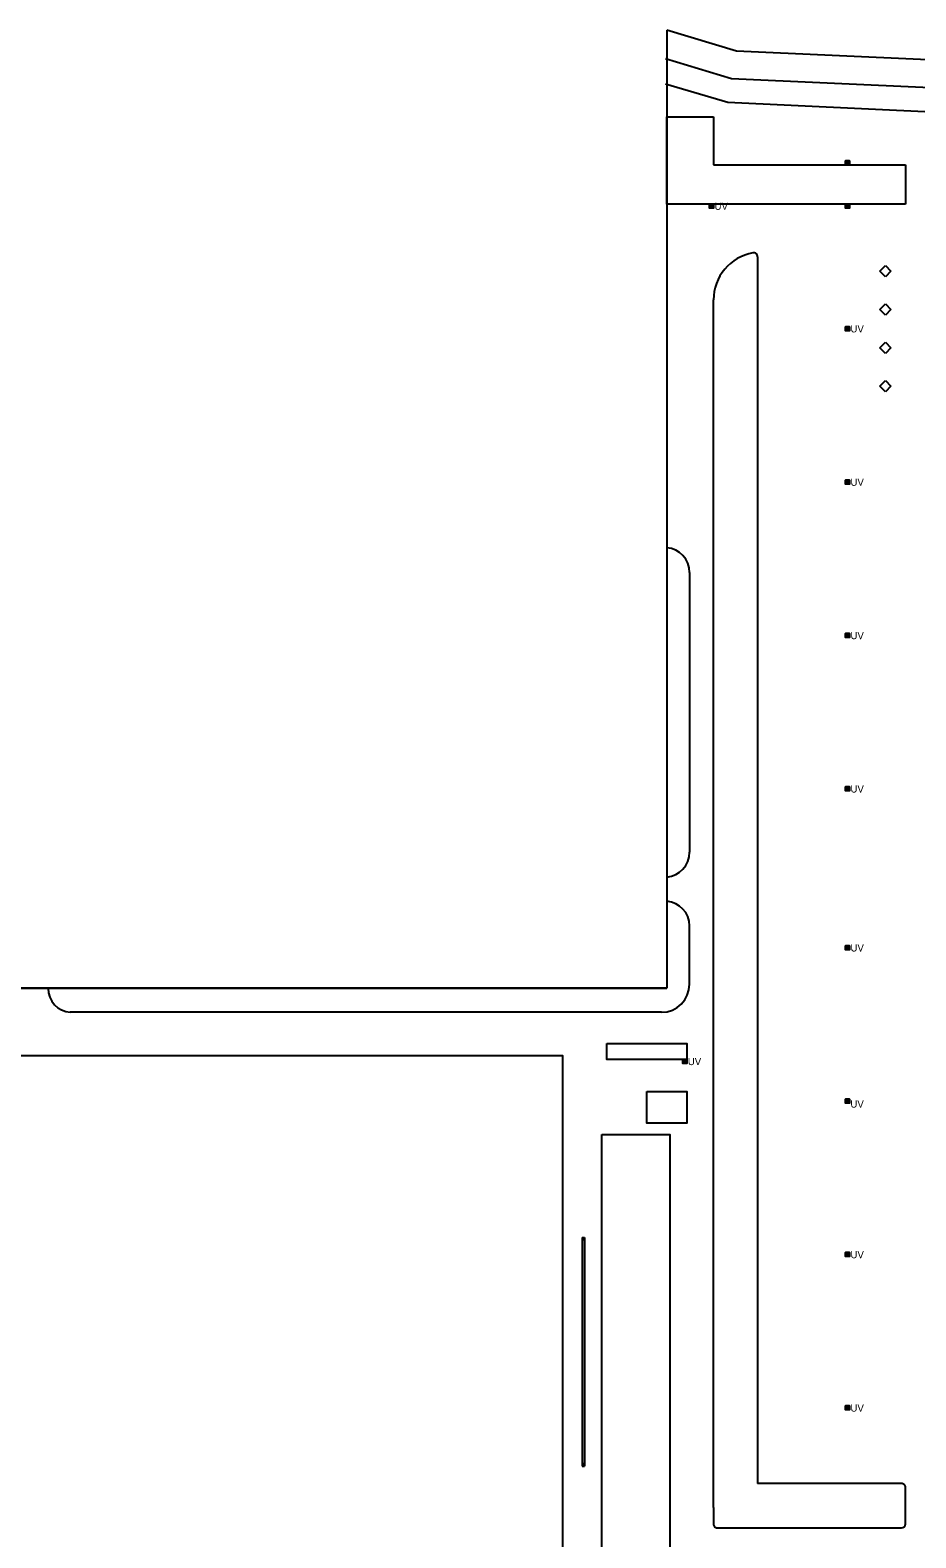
# Model space of a CAD drawing. Extents: x -264222 to -263676, y -1242344 to -1242060.
# Drawn here: x -264039.2 to -263928.3, y -1242248.3 to -1242059.5 of the extents above; entities that cross this region are included whole.
import ezdxf

# ---------------------------------------------------------------- set-up
doc = ezdxf.new("R2010")
doc.units = 0
doc.layers.add('PROJEKT_DRS_OBRUBNIKY_KOMUNIKACIE', color=7, linetype='Continuous')
doc.layers.add('PROJEKT_DRS_UV_STAVBY', color=7, linetype='Continuous')

msp = doc.modelspace()

# ---------------------------------------------------------------- linework, layer by layer
at = {"layer": 'PROJEKT_DRS_OBRUBNIKY_KOMUNIKACIE'}
for p, q in [((-263950.75, -1242062.15), (-263959.47, -1242059.53)), ((-263959.47, -1242059.53), (-263959.47, -1242179.48)), ((-263926.77, -1242063.25), (-263950.75, -1242062.15)), ((-263959.47, -1242071.38), (-263959.47, -1242070.38)), ((-263959.47, -1242070.38), (-263953.62, -1242070.38)), ((-263953.62, -1242070.38), (-263953.62, -1242076.38)), ((-263959.47, -1242076.38), (-263959.47, -1242071.38)), ((-263959.47, -1242081.31), (-263959.47, -1242076.38)), ((-263953.62, -1242076.38), (-263929.58, -1242076.38)), ((-263929.58, -1242076.38), (-263929.58, -1242081.31)), ((-263953.62, -1242081.31), (-263959.47, -1242081.31)), ((-263929.58, -1242081.31), (-263953.62, -1242081.31)), ((-263948.09, -1242087.9), (-263948.09, -1242241.46)), ((-263932.8, -1242089.71), (-263932.09, -1242089)), ((-263932.09, -1242089), (-263931.39, -1242089.71)), ((-263932.09, -1242090.41), (-263932.8, -1242089.71)), ((-263931.39, -1242089.71), (-263932.09, -1242090.41)), ((-263953.62, -1242244.46), (-263953.62, -1242093.31)), ((-263932.8, -1242094.51), (-263932.09, -1242093.8)), ((-263932.09, -1242095.21), (-263932.8, -1242094.51)), ((-263932.09, -1242093.8), (-263931.39, -1242094.51)), ((-263931.39, -1242094.51), (-263932.09, -1242095.21)), ((-263932.8, -1242099.31), (-263932.09, -1242098.6)), ((-263932.09, -1242098.6), (-263931.39, -1242099.31)), ((-263932.09, -1242100.01), (-263932.8, -1242099.31)), ((-263931.39, -1242099.31), (-263932.09, -1242100.01)), ((-263932.8, -1242104.11), (-263932.09, -1242103.4)), ((-263932.09, -1242104.81), (-263932.8, -1242104.11)), ((-263932.09, -1242103.4), (-263931.39, -1242104.11)), ((-263931.39, -1242104.11), (-263932.09, -1242104.81)), ((-263959.47, -1242106.15), (-263959.47, -1242179.48)), ((-263956.62, -1242127.42), (-263956.62, -1242162.45)), ((-263956.62, -1242178.98), (-263956.62, -1242171.65)), ((-263959.47, -1242179.48), (-264131.57, -1242179.48)), ((-264131.57, -1242179.48), (-263959.47, -1242179.48)), ((-263959.47, -1242179.48), (-264077.23, -1242179.48)), ((-263960.12, -1242182.48), (-264034.16, -1242182.48)), ((-263930.08, -1242241.46), (-263948.09, -1242241.46)), ((-263929.58, -1242246.53), (-263929.58, -1242241.96)), ((-263953.62, -1242244.46), (-263953.62, -1242246.53)), ((-263953.12, -1242247.03), (-263930.08, -1242247.03))]:
    msp.add_line(p, q, dxfattribs=at)
for points in [[(-263863.95, -1242065.11), (-263895.45, -1242062.32), (-263915.2, -1242060.92), (-263926.77, -1242063.25), (-263950.75, -1242062.15), (-263959.47, -1242059.53)], [(-263864.26, -1242068.59), (-263895.73, -1242065.81), (-263914.97, -1242064.45), (-263926.5, -1242066.77), (-263951.34, -1242065.63), (-263959.61, -1242063.14)], [(-263864.52, -1242071.58), (-263895.97, -1242068.8), (-263914.78, -1242067.47), (-263926.27, -1242069.78), (-263951.84, -1242068.6), (-263959.61, -1242066.28)], [(-263966.97, -1242186.38), (-263956.97, -1242186.38), (-263956.97, -1242188.38), (-263966.97, -1242188.38), (-263966.97, -1242186.38)], [(-264042.57, -1242294.03), (-263972.47, -1242294.03), (-263972.47, -1242187.93), (-264042.57, -1242187.93), (-264042.57, -1242294.03)], [(-263961.97, -1242192.38), (-263956.97, -1242192.38), (-263956.97, -1242196.38), (-263961.97, -1242196.38), (-263961.97, -1242192.38)], [(-263967.6, -1242197.78), (-263959.1, -1242197.78), (-263959.1, -1242252.18), (-263967.6, -1242252.18), (-263967.6, -1242197.78)]]:
    msp.add_lwpolyline(points, dxfattribs=at)
for centre, radius, start, end in [((-263947.63, -1242093.3), 5.98, 100.0694, 180.066), ((-263948.59, -1242087.9), 0.5, 0, 100.0694), ((-263959.74, -1242127.43), 3.12, 0.1518, 85.0363), ((-263959.74, -1242162.44), 3.12, 274.9637, 359.8482), ((-263959.67, -1242171.63), 3.05, 359.6441, 86.2155), ((-264033.95, -1242179.5), 2.99, 179.75, 266.0314), ((-263960.12, -1242178.98), 3.5, 270, 0), ((-263930.08, -1242241.96), 0.5, 359.9785, 89.9999), ((-263953.12, -1242246.53), 0.5, 179.9525, 270), ((-263930.08, -1242246.53), 0.5, 270, 359.9785)]:
    msp.add_arc(centre, radius, start, end, dxfattribs=at)
at = {"layer": 'PROJEKT_DRS_UV_STAVBY'}
for p, q in [((-263970.07, -1242210.68), (-263969.77, -1242210.68)), ((-263970.07, -1242210.98), (-263969.77, -1242210.68)), ((-263970.07, -1242210.68), (-263969.77, -1242210.99)), ((-263970.07, -1242210.68), (-263970.07, -1242239.28)), ((-263969.77, -1242210.68), (-263969.77, -1242239.28)), ((-263970.07, -1242238.98), (-263969.77, -1242238.98)), ((-263969.77, -1242238.98), (-263970.07, -1242239.28)), ((-263970.07, -1242238.98), (-263969.77, -1242239.28)), ((-263970.07, -1242239.28), (-263969.77, -1242239.28))]:
    msp.add_line(p, q, dxfattribs=at)
for points in [[(-263937.09, -1242076.38), (-263937.09, -1242075.88), (-263936.59, -1242075.88), (-263936.59, -1242076.38), (-263937.09, -1242076.38), (-263936.59, -1242075.88), (-263937.09, -1242075.88), (-263936.59, -1242076.38)], [(-263954.12, -1242081.81), (-263954.12, -1242081.31), (-263953.62, -1242081.31), (-263953.62, -1242081.81), (-263954.12, -1242081.81), (-263953.62, -1242081.31), (-263954.12, -1242081.31), (-263953.62, -1242081.81)], [(-263937.09, -1242081.81), (-263937.09, -1242081.31), (-263936.59, -1242081.31), (-263936.59, -1242081.81), (-263937.09, -1242081.81), (-263936.59, -1242081.31), (-263937.09, -1242081.31), (-263936.59, -1242081.81)], [(-263937.09, -1242097.16), (-263937.09, -1242096.66), (-263936.59, -1242096.66), (-263936.59, -1242097.16), (-263937.09, -1242097.16), (-263936.59, -1242096.66), (-263937.09, -1242096.66), (-263936.59, -1242097.16)], [(-263937.09, -1242116.36), (-263937.09, -1242115.86), (-263936.59, -1242115.86), (-263936.59, -1242116.36), (-263937.09, -1242116.36), (-263936.59, -1242115.86), (-263937.09, -1242115.86), (-263936.59, -1242116.36)], [(-263937.09, -1242135.56), (-263937.09, -1242135.06), (-263936.59, -1242135.06), (-263936.59, -1242135.56), (-263937.09, -1242135.56), (-263936.59, -1242135.06), (-263937.09, -1242135.06), (-263936.59, -1242135.56)], [(-263937.09, -1242154.76), (-263937.09, -1242154.26), (-263936.59, -1242154.26), (-263936.59, -1242154.76), (-263937.09, -1242154.76), (-263936.59, -1242154.26), (-263937.09, -1242154.26), (-263936.59, -1242154.76)], [(-263937.09, -1242174.66), (-263937.09, -1242174.16), (-263936.59, -1242174.16), (-263936.59, -1242174.66), (-263937.09, -1242174.66), (-263936.59, -1242174.16), (-263937.09, -1242174.16), (-263936.59, -1242174.66)], [(-263957.47, -1242188.88), (-263957.47, -1242188.38), (-263956.97, -1242188.38), (-263956.97, -1242188.88), (-263957.47, -1242188.88), (-263956.97, -1242188.38), (-263957.47, -1242188.38), (-263956.97, -1242188.88)], [(-263937.09, -1242193.86), (-263937.09, -1242193.36), (-263936.59, -1242193.36), (-263936.59, -1242193.86), (-263937.09, -1242193.86), (-263936.59, -1242193.36), (-263937.09, -1242193.36), (-263936.59, -1242193.86)], [(-263937.09, -1242213.06), (-263937.09, -1242212.56), (-263936.59, -1242212.56), (-263936.59, -1242213.06), (-263937.09, -1242213.06), (-263936.59, -1242212.56), (-263937.09, -1242212.56), (-263936.59, -1242213.06)], [(-263937.09, -1242232.26), (-263937.09, -1242231.76), (-263936.59, -1242231.76), (-263936.59, -1242232.26), (-263937.09, -1242232.26), (-263936.59, -1242231.76), (-263937.09, -1242231.76), (-263936.59, -1242232.26)]]:
    msp.add_lwpolyline(points, dxfattribs=at)

# ---------------------------------------------------------------- texts
for p in [(-263953.48, -1242082.02), (-263936.46, -1242097.37), (-263936.46, -1242116.57), (-263936.46, -1242135.77), (-263936.46, -1242154.97), (-263936.46, -1242174.87), (-263956.83, -1242189.09), (-263936.47, -1242194.41), (-263936.46, -1242213.27), (-263936.46, -1242232.47)]:
    msp.add_text('UV', height=0.9, rotation=359.8587, dxfattribs=at).set_placement(p)

doc.saveas('drawing.dxf')
